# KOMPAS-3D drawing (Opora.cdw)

Views: Вид 1, Вид 2, Вид 3, Вид 4
Referenced files in F:\Учеба\6 семестр\Литейное производство\курсовая\: Опора.cdw
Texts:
  Опора
  Царь
  POLYTEH
  Ra3,2
  Ra1,6
  Rz20
  Александров
  Морозова
  СЧ 20 ГОСТ 14 12-85
  СПбПУ
  гр. № 33314/1
Dimensions and other numbers on the sheet: 260; 300; 400; 70; 180; 50; 40; 200; 1; 0,8; 20; 35; 1:1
